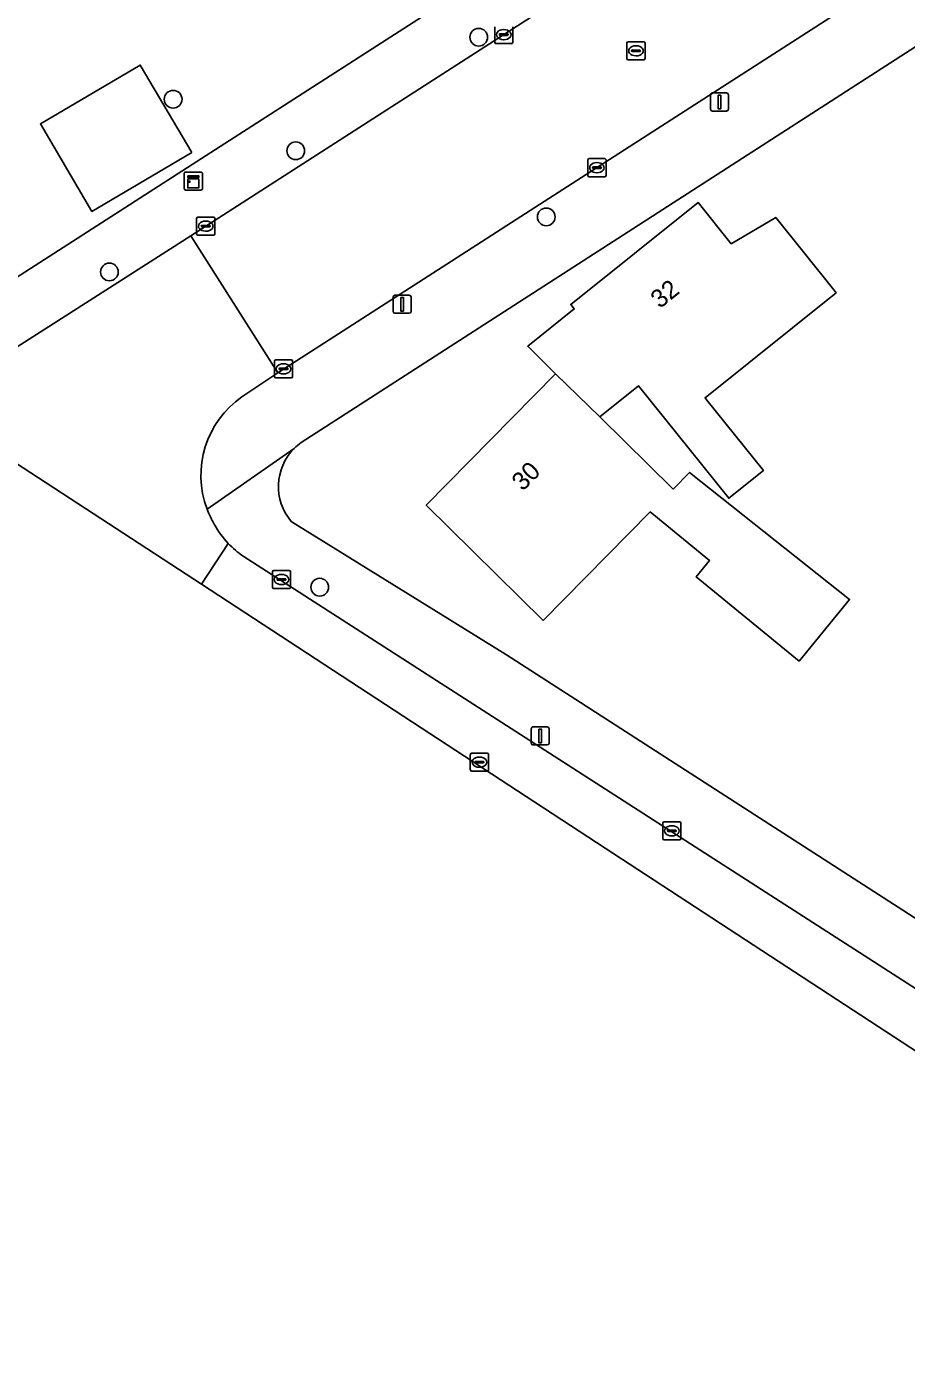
# Model space of a CAD drawing. Extents: x 160157 to 160921, y 381516 to 382045.
# Drawn here: x 160304.8 to 160353.4, y 381588.2 to 381662.4 of the extents above; entities that cross this region are included whole.
import ezdxf

# ---------------------------------------------------------------- set-up
doc = ezdxf.new("R2010")
doc.units = 0
for name, color, linetype in [('IMGEO_Boom', 7, 'Continuous'), ('IMGEO_Erf', 7, 'Continuous'), ('IMGEO_Kast', 7, 'Continuous'), ('IMGEO_Kolk', 7, 'Continuous'), ('IMGEO_Lichtmast', 7, 'Continuous'), ('IMGEO_Muur', 7, 'Continuous'), ('IMGEO_Pand', 7, 'Continuous'), ('IMGEO_Pand_nummerreeks', 7, 'Continuous'), ('IMGEO_Rijbaan_lokaal_open', 7, 'Continuous'), ('IMGEO_Rioolput', 7, 'Continuous'), ('IMGEO_Voetpad_open', 7, 'Continuous')]:
    doc.layers.add(name, color=color, linetype=linetype)

msp = doc.modelspace()

# ---------------------------------------------------------------- linework, layer by layer
at = {"layer": 'IMGEO_Boom'}
for centre in [(160329.784, 381661.874), (160312.92, 381658.45), (160319.687, 381655.603), (160333.513, 381651.955), (160309.401, 381648.915), (160321.009, 381631.517)]:
    msp.add_circle(centre, 0.489, dxfattribs=at)
at = {"layer": 'IMGEO_Erf'}
for points in [[(160274.895, 381634.961), (160282.085, 381637.13), (160287.207, 381639.31), (160293.877, 381642.708), (160303.442, 381648.074), (160315.003, 381655.51), (160335.072, 381668.419), (160355.613, 381681.967)], [(160378.904, 381677.285), (160355.248, 381662.223), (160319.993, 381639.498)], [(160319.436, 381635.145), (160331.317, 381627.79), (160361.156, 381608.556), (160362.318, 381609.828), (160405.188, 381582.297), (160414.171, 381576.508), (160427.676, 381597.123), (160427.729, 381597.121), (160427.898, 381597.365), (160424.706, 381599.434), (160411.1, 381608.252), (160410.955, 381608.346), (160409.818, 381609.084), (160392.312, 381620.441), (160387.378, 381623.641), (160380.613, 381628.03), (160378.993, 381629.081)]]:
    msp.add_lwpolyline(points, dxfattribs=at)
for points in [[(160313.95, 381655.506), (160308.44, 381652.257), (160305.592, 381657.085), (160311.103, 381660.335)], [(160350.255, 381630.842), (160347.469, 381627.435), (160341.787, 381632.082), (160342.528, 381632.988), (160339.245, 381635.674), (160333.346, 381629.682), (160326.888, 381636.039), (160334.028, 381643.292), (160332.486, 381644.811), (160335.06, 381646.875), (160334.863, 381647.122), (160341.894, 381652.757), (160343.723, 381650.475), (160346.177, 381651.926), (160349.304, 381648.024), (160349.512, 381647.766), (160342.279, 381641.969), (160342.383, 381641.839), (160345.494, 381637.958), (160343.58, 381636.423), (160338.601, 381642.635), (160336.465, 381640.924), (160340.518, 381636.934), (160341.424, 381637.855)]]:
    msp.add_lwpolyline(points, close=True, dxfattribs=at)
for centre, radius, start, end in [((160321.701, 381637.068), 2.971, 135.08645, 220.32664), ((160321.747, 381637.01), 3.045, 125.18651, 134.93506)]:
    msp.add_arc(centre, radius, start, end, dxfattribs=at)
at = {"layer": 'IMGEO_Kast'}
for p, q in [((160313.61, 381654.433), (160314.451, 381654.433)), ((160314.451, 381654.433), (160313.61, 381654.433)), ((160313.535, 381653.508), (160313.535, 381654.349)), ((160313.535, 381654.349), (160313.535, 381653.508)), ((160314.535, 381654.358), (160314.535, 381653.517)), ((160314.535, 381653.517), (160314.535, 381654.358)), ((160314.46, 381653.433), (160313.619, 381653.433)), ((160313.619, 381653.433), (160314.46, 381653.433))]:
    msp.add_line(p, q, dxfattribs=at)
for points in [[(160313.73, 381654.223), (160314.33, 381654.223), (160314.33, 381654.138), (160313.73, 381654.138), (160313.73, 381654.223)], [(160313.73, 381654.048), (160314.33, 381654.048), (160314.33, 381653.559), (160313.73, 381653.559), (160313.73, 381654.048)]]:
    msp.add_lwpolyline(points, dxfattribs=at)
msp.add_circle((160313.814, 381653.897), 0.0377, dxfattribs=at)
for centre, start, end in [((160313.613, 381654.355), 92.4484, 184.28452), ((160313.613, 381654.355), 92.4484, 184.28452), ((160314.457, 381654.355), 2.4484, 94.28452), ((160314.457, 381654.355), 2.4484, 94.28452), ((160313.613, 381653.511), 182.4484, 274.28452), ((160313.613, 381653.511), 182.4484, 274.28452), ((160314.457, 381653.511), 272.4484, 4.28452), ((160314.457, 381653.511), 272.4484, 4.28452)]:
    msp.add_arc(centre, 0.0779, start, end, dxfattribs=at)
at = {"layer": 'IMGEO_Kolk'}
for p, q in [((160330.665, 381661.591), (160330.665, 381662.443)), ((160330.924, 381662.011), (160330.924, 381662.023)), ((160331.362, 381661.974), (160330.964, 381661.974)), ((160330.967, 381662.06), (160331.365, 381662.06)), ((160331.153, 381662.297), (160331.178, 381662.297)), ((160331.408, 381662.023), (160331.408, 381662.011)), ((160331.666, 381662.443), (160331.666, 381661.591)), ((160331.592, 381661.517), (160330.74, 381661.517)), ((160331.176, 381661.737), (160331.151, 381661.737)), ((160335.884, 381655.171), (160336.736, 381655.171)), ((160335.809, 381654.245), (160335.809, 381655.097)), ((160336.068, 381654.665), (160336.068, 381654.677)), ((160336.506, 381654.628), (160336.108, 381654.628)), ((160336.111, 381654.714), (160336.509, 381654.714)), ((160336.32, 381654.391), (160336.295, 381654.391)), ((160336.297, 381654.951), (160336.322, 381654.951)), ((160336.552, 381654.677), (160336.552, 381654.665)), ((160336.81, 381655.097), (160336.81, 381654.245)), ((160336.736, 381654.171), (160335.884, 381654.171)), ((160314.215, 381651.02), (160314.215, 381651.872)), ((160314.29, 381651.946), (160315.142, 381651.946)), ((160314.474, 381651.44), (160314.474, 381651.452)), ((160314.912, 381651.403), (160314.514, 381651.403)), ((160314.517, 381651.489), (160314.915, 381651.489)), ((160314.703, 381651.726), (160314.728, 381651.726)), ((160314.958, 381651.452), (160314.958, 381651.44)), ((160315.216, 381651.872), (160315.216, 381651.02)), ((160315.142, 381650.946), (160314.29, 381650.946)), ((160314.726, 381651.166), (160314.701, 381651.166)), ((160318.512, 381643.14), (160318.512, 381643.992)), ((160318.587, 381644.066), (160319.439, 381644.066)), ((160319.513, 381643.992), (160319.513, 381643.14)), ((160318.771, 381643.56), (160318.771, 381643.572)), ((160319.209, 381643.523), (160318.811, 381643.523)), ((160318.814, 381643.609), (160319.212, 381643.609)), ((160319.023, 381643.286), (160318.998, 381643.286)), ((160319, 381643.846), (160319.025, 381643.846)), ((160319.255, 381643.572), (160319.255, 381643.56)), ((160319.439, 381643.066), (160318.587, 381643.066)), ((160318.397, 381631.514), (160318.397, 381632.366)), ((160318.472, 381632.44), (160319.324, 381632.44)), ((160318.885, 381632.22), (160318.91, 381632.22)), ((160319.398, 381632.366), (160319.398, 381631.514)), ((160319.324, 381631.44), (160318.472, 381631.44)), ((160318.656, 381631.934), (160318.656, 381631.946)), ((160319.094, 381631.897), (160318.696, 381631.897)), ((160318.699, 381631.983), (160319.097, 381631.983)), ((160318.908, 381631.66), (160318.883, 381631.66)), ((160319.14, 381631.946), (160319.14, 381631.934)), ((160339.942, 381617.643), (160339.942, 381618.495)), ((160340.017, 381618.569), (160340.869, 381618.569)), ((160340.201, 381618.063), (160340.201, 381618.075)), ((160340.639, 381618.026), (160340.241, 381618.026)), ((160340.244, 381618.112), (160340.642, 381618.112)), ((160340.43, 381618.349), (160340.455, 381618.349)), ((160340.685, 381618.075), (160340.685, 381618.063)), ((160340.943, 381618.495), (160340.943, 381617.643)), ((160340.869, 381617.569), (160340.017, 381617.569)), ((160340.453, 381617.789), (160340.428, 381617.789))]:
    msp.add_line(p, q, dxfattribs=at)
for points in [[(160330.665, 381661.591), (160330.665, 381662.443)], [(160331.666, 381662.443), (160331.666, 381661.591)], [(160331.592, 381661.517), (160330.74, 381661.517)], [(160335.884, 381655.171), (160336.736, 381655.171)], [(160335.809, 381654.245), (160335.809, 381655.097)], [(160336.81, 381655.097), (160336.81, 381654.245)], [(160336.736, 381654.171), (160335.884, 381654.171)], [(160314.215, 381651.02), (160314.215, 381651.872)], [(160314.29, 381651.946), (160315.142, 381651.946)], [(160315.216, 381651.872), (160315.216, 381651.02)], [(160315.142, 381650.946), (160314.29, 381650.946)], [(160318.512, 381643.14), (160318.512, 381643.992)], [(160318.587, 381644.066), (160319.439, 381644.066)], [(160319.513, 381643.992), (160319.513, 381643.14)], [(160319.439, 381643.066), (160318.587, 381643.066)], [(160318.397, 381631.514), (160318.397, 381632.366)], [(160318.472, 381632.44), (160319.324, 381632.44)], [(160319.398, 381632.366), (160319.398, 381631.514)], [(160319.324, 381631.44), (160318.472, 381631.44)], [(160339.942, 381617.643), (160339.942, 381618.495)], [(160340.017, 381618.569), (160340.869, 381618.569)], [(160340.943, 381618.495), (160340.943, 381617.643)], [(160340.869, 381617.569), (160340.017, 381617.569)]]:
    msp.add_lwpolyline(points, dxfattribs=at)
for centre, radius, start, end in [((160330.964, 381662.02), 0.0403, 85.87752, 175.75265), ((160330.961, 381662.01), 0.0366, 178.93798, 274.71019), ((160331.365, 381662.017), 0.043, 264.86636, 352.45326), ((160331.369, 381662.022), 0.0386, 1.73085, 96.63898), ((160330.742, 381661.593), 0.0765, 181.55205, 268.44795), ((160330.742, 381661.593), 0.0765, 181.55205, 268.44795), ((160331.59, 381661.593), 0.0765, 271.55205, 358.44795), ((160331.59, 381661.593), 0.0765, 271.55205, 358.44795), ((160335.886, 381655.095), 0.0765, 91.55205, 178.44795), ((160335.886, 381655.095), 0.0765, 91.55205, 178.44795), ((160336.734, 381655.095), 0.0765, 1.55205, 88.44795), ((160336.734, 381655.095), 0.0765, 1.55205, 88.44795), ((160336.108, 381654.674), 0.0403, 85.87752, 175.75265), ((160336.105, 381654.664), 0.0366, 178.93798, 274.71019), ((160336.509, 381654.671), 0.043, 264.86636, 352.45326), ((160336.513, 381654.676), 0.0386, 1.73085, 96.63898), ((160335.886, 381654.247), 0.0765, 181.55205, 268.44795), ((160335.886, 381654.247), 0.0765, 181.55205, 268.44795), ((160336.734, 381654.247), 0.0765, 271.55205, 358.44795), ((160336.734, 381654.247), 0.0765, 271.55205, 358.44795), ((160314.292, 381651.87), 0.0765, 91.55205, 178.44795), ((160314.292, 381651.87), 0.0765, 91.55205, 178.44795), ((160314.514, 381651.449), 0.0403, 85.87752, 175.75265), ((160314.511, 381651.439), 0.0366, 178.93798, 274.71019), ((160314.915, 381651.446), 0.043, 264.86636, 352.45326), ((160314.919, 381651.451), 0.0386, 1.73085, 96.63898), ((160315.14, 381651.87), 0.0765, 1.55205, 88.44795), ((160315.14, 381651.87), 0.0765, 1.55205, 88.44795), ((160314.292, 381651.022), 0.0765, 181.55205, 268.44795), ((160314.292, 381651.022), 0.0765, 181.55205, 268.44795), ((160315.14, 381651.022), 0.0765, 271.55205, 358.44795), ((160315.14, 381651.022), 0.0765, 271.55205, 358.44795), ((160318.589, 381643.99), 0.0765, 91.55205, 178.44795), ((160318.589, 381643.99), 0.0765, 91.55205, 178.44795), ((160319.437, 381643.99), 0.0765, 1.55205, 88.44795), ((160319.437, 381643.99), 0.0765, 1.55205, 88.44795), ((160318.811, 381643.569), 0.0403, 85.87752, 175.75265), ((160318.808, 381643.559), 0.0366, 178.93798, 274.71019), ((160319.212, 381643.566), 0.043, 264.86636, 352.45326), ((160319.216, 381643.571), 0.0386, 1.73085, 96.63898), ((160318.589, 381643.142), 0.0765, 181.55205, 268.44795), ((160318.589, 381643.142), 0.0765, 181.55205, 268.44795), ((160319.437, 381643.142), 0.0765, 271.55205, 358.44795), ((160319.437, 381643.142), 0.0765, 271.55205, 358.44795), ((160318.474, 381632.364), 0.0765, 91.55205, 178.44795), ((160318.474, 381632.364), 0.0765, 91.55205, 178.44795), ((160319.322, 381632.364), 0.0765, 1.55205, 88.44795), ((160319.322, 381632.364), 0.0765, 1.55205, 88.44795), ((160318.474, 381631.516), 0.0765, 181.55205, 268.44795), ((160318.474, 381631.516), 0.0765, 181.55205, 268.44795), ((160318.696, 381631.943), 0.0403, 85.87752, 175.75265), ((160318.693, 381631.933), 0.0366, 178.93798, 274.71019), ((160319.097, 381631.94), 0.043, 264.86636, 352.45326), ((160319.101, 381631.945), 0.0386, 1.73085, 96.63898), ((160319.322, 381631.516), 0.0765, 271.55205, 358.44795), ((160319.322, 381631.516), 0.0765, 271.55205, 358.44795), ((160340.019, 381618.493), 0.0765, 91.55205, 178.44795), ((160340.019, 381618.493), 0.0765, 91.55205, 178.44795), ((160340.241, 381618.072), 0.0403, 85.87752, 175.75265), ((160340.238, 381618.062), 0.0366, 178.93798, 274.71019), ((160340.642, 381618.069), 0.043, 264.86636, 352.45326), ((160340.646, 381618.074), 0.0386, 1.73085, 96.63898), ((160340.867, 381618.493), 0.0765, 1.55205, 88.44795), ((160340.867, 381618.493), 0.0765, 1.55205, 88.44795), ((160340.019, 381617.645), 0.0765, 181.55205, 268.44795), ((160340.019, 381617.645), 0.0765, 181.55205, 268.44795), ((160340.867, 381617.645), 0.0765, 271.55205, 358.44795), ((160340.867, 381617.645), 0.0765, 271.55205, 358.44795)]:
    msp.add_arc(centre, radius, start, end, dxfattribs=at)
for centre, major_axis, ratio, start_param, end_param in [((160331.152, 381662.017), (-0.387, 0.002), 0.722429, 4.712389, 7.853982), ((160331.177, 381662.017), (-0.39, 0.002), 0.717154, 1.570796, 4.712389), ((160336.296, 381654.671), (-0.387, 0.002), 0.722429, 4.712389, 7.853982), ((160336.321, 381654.671), (-0.39, 0.002), 0.717154, 1.570796, 4.712389), ((160314.702, 381651.446), (-0.387, 0.002), 0.722429, 4.712389, 7.853982), ((160314.727, 381651.446), (-0.39, 0.002), 0.717154, 1.570796, 4.712389), ((160318.999, 381643.566), (-0.387, 0.002), 0.722429, 4.712389, 7.853982), ((160319.024, 381643.566), (-0.39, 0.002), 0.717154, 1.570796, 4.712389), ((160318.884, 381631.94), (-0.387, 0.002), 0.722429, 4.712389, 7.853982), ((160318.909, 381631.94), (-0.39, 0.002), 0.717154, 1.570796, 4.712389), ((160340.429, 381618.069), (-0.387, 0.002), 0.722429, 4.712389, 7.853982), ((160340.454, 381618.069), (-0.39, 0.002), 0.717154, 1.570796, 4.712389)]:
    msp.add_ellipse(centre, major_axis=major_axis, ratio=ratio, start_param=start_param, end_param=end_param, dxfattribs=at)
at = {"layer": 'IMGEO_Lichtmast'}
for p, q in [((160342.576, 381657.897), (160342.576, 381658.697)), ((160342.576, 381658.697), (160342.576, 381657.897)), ((160342.676, 381658.797), (160343.466, 381658.797)), ((160343.466, 381658.797), (160342.676, 381658.797)), ((160343.566, 381658.697), (160343.566, 381657.897)), ((160343.566, 381657.897), (160343.566, 381658.697)), ((160343.466, 381657.797), (160342.676, 381657.797)), ((160342.676, 381657.797), (160343.466, 381657.797)), ((160325.062, 381646.735), (160325.062, 381647.535)), ((160325.062, 381647.535), (160325.062, 381646.735)), ((160325.162, 381647.635), (160325.952, 381647.635)), ((160325.952, 381647.635), (160325.162, 381647.635)), ((160326.052, 381647.535), (160326.052, 381646.735)), ((160326.052, 381646.735), (160326.052, 381647.535)), ((160325.952, 381646.635), (160325.162, 381646.635)), ((160325.162, 381646.635), (160325.952, 381646.635)), ((160332.678, 381622.907), (160332.678, 381623.707)), ((160332.678, 381623.707), (160332.678, 381622.907)), ((160332.778, 381623.807), (160333.568, 381623.807)), ((160333.568, 381623.807), (160332.778, 381623.807)), ((160333.668, 381623.707), (160333.668, 381622.907)), ((160333.668, 381622.907), (160333.668, 381623.707)), ((160333.568, 381622.807), (160332.778, 381622.807)), ((160332.778, 381622.807), (160333.568, 381622.807))]:
    msp.add_line(p, q, dxfattribs=at)
for points in [[(160342.996, 381658.672), (160343.146, 381658.672), (160343.146, 381657.922), (160342.996, 381657.922), (160342.996, 381658.672)], [(160325.482, 381647.51), (160325.632, 381647.51), (160325.632, 381646.76), (160325.482, 381646.76), (160325.482, 381647.51)], [(160333.098, 381623.682), (160333.248, 381623.682), (160333.248, 381622.932), (160333.098, 381622.932), (160333.098, 381623.682)]]:
    msp.add_lwpolyline(points, dxfattribs=at)
for centre, start, end in [((160342.676, 381658.697), 90, 180), ((160342.676, 381658.697), 90, 180), ((160343.466, 381658.697), 0, 90), ((160343.466, 381658.697), 360, 90), ((160342.676, 381657.897), 180, 270), ((160342.676, 381657.897), 180, 270), ((160343.466, 381657.897), 270, 0), ((160343.466, 381657.897), 270, 0), ((160325.162, 381647.535), 90, 180), ((160325.162, 381647.535), 90, 180), ((160325.952, 381647.535), 0, 90), ((160325.952, 381647.535), 360, 90), ((160325.162, 381646.735), 180, 270), ((160325.162, 381646.735), 180, 270), ((160325.952, 381646.735), 270, 0), ((160325.952, 381646.735), 270, 0), ((160332.778, 381623.707), 90, 180), ((160332.778, 381623.707), 90, 180), ((160333.568, 381623.707), 0, 90), ((160333.568, 381623.707), 360, 90), ((160332.778, 381622.907), 180, 270), ((160332.778, 381622.907), 180, 270), ((160333.568, 381622.907), 270, 0), ((160333.568, 381622.907), 270, 0)]:
    msp.add_arc(centre, 0.1, start, end, dxfattribs=at)
at = {"layer": 'IMGEO_Muur'}
for points in [[(160355.37, 381682.336), (160355.613, 381681.967), (160335.072, 381668.419), (160315.003, 381655.51), (160303.442, 381648.074)], [(160362.318, 381609.828), (160361.156, 381608.556), (160331.317, 381627.79)]]:
    msp.add_lwpolyline(points, dxfattribs=at)
at = {"layer": 'IMGEO_Pand'}
for points in [[(160313.95, 381655.506), (160311.103, 381660.335), (160305.592, 381657.085), (160308.44, 381652.257)], [(160336.465, 381640.924), (160338.601, 381642.635), (160343.58, 381636.423), (160345.494, 381637.958), (160342.383, 381641.839), (160342.279, 381641.969), (160349.512, 381647.766), (160349.304, 381648.024), (160346.177, 381651.926), (160343.723, 381650.475), (160341.894, 381652.757), (160334.863, 381647.122), (160335.06, 381646.875), (160332.486, 381644.811), (160334.028, 381643.292)], [(160336.465, 381640.924), (160334.028, 381643.292), (160326.888, 381636.039), (160333.346, 381629.682), (160339.245, 381635.674), (160342.528, 381632.988), (160341.787, 381632.082), (160347.469, 381627.435), (160350.255, 381630.842), (160341.424, 381637.855), (160340.518, 381636.934)]]:
    msp.add_lwpolyline(points, close=True, dxfattribs=at)
at = {"layer": 'IMGEO_Rijbaan_lokaal_open'}
for points in [[(160368.481, 381686.027), (160361.929, 381681.811), (160356.85, 381678.543), (160313.889, 381650.901), (160318.701, 381643.354), (160328.02, 381649.339), (160331.601, 381651.639), (160355.653, 381667.141), (160362.994, 381671.837), (160367.056, 381674.482), (160370.346, 381676.606), (160373.638, 381678.699)], [(160316.716, 381642.028), (160318.701, 381643.354), (160313.889, 381650.901), (160294.195, 381638.32), (160297.121, 381633.596), (160304.225, 381638.384), (160314.492, 381631.674)], [(160314.492, 381631.674), (160315.96, 381633.935)], [(160315.96, 381633.935), (160314.492, 381631.674), (160336.288, 381617.43), (160360.481, 381601.619), (160420.655, 381562.912), (160425.691, 381520.323)], [(160429.107, 381525.876), (160428.448, 381529.973), (160425.993, 381545.238), (160424.108, 381556.964), (160422.828, 381564.957), (160416.716, 381568.924), (160409.388, 381573.68), (160408.723, 381574.112), (160407.685, 381574.769), (160404.488, 381576.764), (160394.652, 381583.11), (160389.591, 381586.361), (160379.608, 381592.774), (160374.562, 381596.051), (160364.374, 381602.611), (160361.213, 381604.662), (160316.781, 381633.231)]]:
    msp.add_lwpolyline(points, dxfattribs=at)
for centre, radius, start, end in [((160319.748, 381637.687), 5.295, 124.9346, 200.57842), ((160319.877, 381637.752), 5.438, 200.74134, 210.43727), ((160319.781, 381637.524), 5.242, 208.82013, 223.20895), ((160319.762, 381637.539), 5.239, 223.46236, 235.31207)]:
    msp.add_arc(centre, radius, start, end, dxfattribs=at)
at = {"layer": 'IMGEO_Rioolput'}
for p, q in [((160337.963, 381660.698), (160337.963, 381661.55)), ((160338.038, 381661.624), (160338.89, 381661.624)), ((160338.222, 381661.118), (160338.222, 381661.13)), ((160338.66, 381661.081), (160338.262, 381661.081)), ((160338.265, 381661.167), (160338.663, 381661.167)), ((160338.451, 381661.404), (160338.476, 381661.404)), ((160338.706, 381661.13), (160338.706, 381661.118)), ((160338.964, 381661.55), (160338.964, 381660.698)), ((160338.89, 381660.624), (160338.038, 381660.624)), ((160338.474, 381660.844), (160338.449, 381660.844)), ((160329.321, 381621.433), (160329.321, 381622.285)), ((160329.396, 381622.359), (160330.248, 381622.359)), ((160329.58, 381621.853), (160329.58, 381621.865)), ((160330.018, 381621.816), (160329.62, 381621.816)), ((160329.623, 381621.902), (160330.021, 381621.902)), ((160329.809, 381622.139), (160329.834, 381622.139)), ((160330.064, 381621.865), (160330.064, 381621.853)), ((160330.322, 381622.285), (160330.322, 381621.433)), ((160330.248, 381621.359), (160329.396, 381621.359)), ((160329.832, 381621.579), (160329.807, 381621.579))]:
    msp.add_line(p, q, dxfattribs=at)
for points in [[(160337.963, 381660.698), (160337.963, 381661.55)], [(160338.038, 381661.624), (160338.89, 381661.624)], [(160338.964, 381661.55), (160338.964, 381660.698)], [(160338.89, 381660.624), (160338.038, 381660.624)], [(160329.321, 381621.433), (160329.321, 381622.285)], [(160329.396, 381622.359), (160330.248, 381622.359)], [(160330.322, 381622.285), (160330.322, 381621.433)], [(160330.248, 381621.359), (160329.396, 381621.359)]]:
    msp.add_lwpolyline(points, dxfattribs=at)
for centre, radius, start, end in [((160338.04, 381661.548), 0.0765, 91.55205, 178.44795), ((160338.04, 381661.548), 0.0765, 91.55205, 178.44795), ((160338.262, 381661.127), 0.0403, 85.87752, 175.75265), ((160338.259, 381661.117), 0.0366, 178.93798, 274.71019), ((160338.663, 381661.124), 0.043, 264.86636, 352.45326), ((160338.667, 381661.129), 0.0386, 1.73085, 96.63898), ((160338.888, 381661.548), 0.0765, 1.55205, 88.44795), ((160338.888, 381661.548), 0.0765, 1.55205, 88.44795), ((160338.04, 381660.7), 0.0765, 181.55205, 268.44795), ((160338.04, 381660.7), 0.0765, 181.55205, 268.44795), ((160338.888, 381660.7), 0.0765, 271.55205, 358.44795), ((160338.888, 381660.7), 0.0765, 271.55205, 358.44795), ((160329.398, 381622.283), 0.0765, 91.55205, 178.44795), ((160329.398, 381622.283), 0.0765, 91.55205, 178.44795), ((160329.62, 381621.862), 0.0403, 85.87752, 175.75265), ((160329.617, 381621.852), 0.0366, 178.93798, 274.71019), ((160330.021, 381621.859), 0.043, 264.86636, 352.45326), ((160330.025, 381621.864), 0.0386, 1.73085, 96.63898), ((160330.246, 381622.283), 0.0765, 1.55205, 88.44795), ((160330.246, 381622.283), 0.0765, 1.55205, 88.44795), ((160329.398, 381621.435), 0.0765, 181.55205, 268.44795), ((160329.398, 381621.435), 0.0765, 181.55205, 268.44795), ((160330.246, 381621.435), 0.0765, 271.55205, 358.44795), ((160330.246, 381621.435), 0.0765, 271.55205, 358.44795)]:
    msp.add_arc(centre, radius, start, end, dxfattribs=at)
for centre, major_axis, ratio, start_param, end_param in [((160338.45, 381661.124), (-0.387, 0.002), 0.722429, 4.712389, 7.853982), ((160338.475, 381661.124), (-0.39, 0.002), 0.717154, 1.570796, 4.712389), ((160329.808, 381621.859), (-0.387, 0.002), 0.722429, 4.712389, 7.853982), ((160329.833, 381621.859), (-0.39, 0.002), 0.717154, 1.570796, 4.712389)]:
    msp.add_ellipse(centre, major_axis=major_axis, ratio=ratio, start_param=start_param, end_param=end_param, dxfattribs=at)
at = {"layer": 'IMGEO_Voetpad_open'}
for points in [[(160369.922, 381690.69), (160360.83, 381685.003), (160360.513, 381685.494), (160355.37, 381682.336), (160355.613, 381681.967), (160335.072, 381668.419), (160315.003, 381655.51), (160303.442, 381648.074), (160293.877, 381642.708), (160287.207, 381639.31), (160282.085, 381637.13), (160274.895, 381634.961), (160273.476, 381634.643), (160276.764, 381630.165)], [(160280.872, 381629.729), (160286.577, 381633.43), (160292.105, 381636.955), (160294.195, 381638.32), (160313.889, 381650.901), (160356.85, 381678.543), (160361.929, 381681.811), (160368.481, 381686.027)], [(160373.638, 381678.699), (160370.346, 381676.606), (160367.056, 381674.482), (160362.994, 381671.837), (160355.653, 381667.141), (160331.601, 381651.639), (160328.02, 381649.339), (160318.701, 381643.354), (160316.716, 381642.028)], [(160319.993, 381639.498), (160355.248, 381662.223)], [(160314.791, 381635.826), (160319.597, 381639.165)], [(160319.597, 381639.165), (160314.791, 381635.826)], [(160362.318, 381609.828), (160361.156, 381608.556), (160331.317, 381627.79), (160319.436, 381635.145)], [(160316.781, 381633.231), (160361.213, 381604.662), (160364.374, 381602.611), (160374.562, 381596.051), (160379.608, 381592.774), (160389.591, 381586.361), (160394.652, 381583.11), (160404.488, 381576.764), (160407.685, 381574.769), (160408.723, 381574.112), (160409.388, 381573.68), (160416.716, 381568.924), (160422.828, 381564.957)]]:
    msp.add_lwpolyline(points, dxfattribs=at)
for centre, radius, start, end in [((160319.748, 381637.687), 5.295, 124.9346, 200.57842), ((160321.701, 381637.068), 2.971, 135.08645, 220.32664), ((160321.747, 381637.01), 3.045, 125.18651, 134.93506), ((160319.877, 381637.752), 5.438, 200.74134, 210.43727), ((160319.781, 381637.524), 5.242, 208.82013, 223.20895), ((160319.762, 381637.539), 5.239, 223.46236, 235.31207)]:
    msp.add_arc(centre, radius, start, end, dxfattribs=at)

# ---------------------------------------------------------------- texts
at = {"layer": 'IMGEO_Pand_nummerreeks'}
for s, rotation, p in [('32', 38.71046, (160339.783, 381646.862)), ('30', 45.44982, (160332.218, 381636.778))]:
    msp.add_text(s, height=1, rotation=rotation, dxfattribs=at).set_placement(p)

doc.saveas('drawing.dxf')
